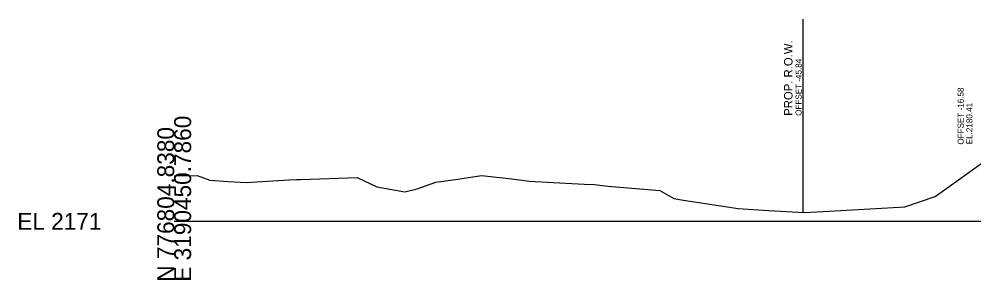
# Model space of a CAD drawing. Extents: x -26 to 303, y -25 to 5046.
# Drawn here: x -25.7 to 132.5, y 3990.3 to 4033.5 of the extents above; entities that cross this region are included whole.
import ezdxf

# ---------------------------------------------------------------- set-up
doc = ezdxf.new("R2010")
doc.units = 0
for name, color, linetype in [('DESIGN - ROW - Right-of-Way and Easement Labels', 7, 'Continuous'), ('DESIGN - ROW - Right-of-Way Linework', 7, 'Continuous'), ('DESIGN - SHEET - Light Grid', 7, 'Continuous'), ('DESIGN - TYPICAL - Slope Tie Text', 7, 'Continuous'), ('SURVEY - GROUND - Top of Ground', 7, 'Continuous')]:
    doc.layers.add(name, color=color, linetype=linetype)

msp = doc.modelspace()

# ---------------------------------------------------------------- linework, layer by layer
at = {"layer": 'DESIGN - ROW - Right-of-Way Linework'}
msp.add_line((104.16, 4001.47), (104.16, 4033.47), dxfattribs=at)
at = {"layer": 'DESIGN - SHEET - Light Grid'}
msp.add_line((0, 4000), (150, 4000), dxfattribs=at)
at = {"layer": 'SURVEY - GROUND - Top of Ground'}
msp.add_lwpolyline([(0, 4007.52), (3.82, 4007.56), (5.92, 4006.81), (8.92, 4006.59), (11.91, 4006.41), (19.01, 4006.85), (20.28, 4006.94), (20.95, 4006.95), (30.32, 4007.23), (33.55, 4005.73), (38.22, 4004.89), (40.24, 4005.39), (43.36, 4006.46), (47, 4007), (50.9, 4007.57), (55.92, 4007.05), (58.79, 4006.65), (67.91, 4006.16), (69.61, 4006.12), (71.8, 4005.84), (80.41, 4005.13), (82.78, 4003.76), (84.37, 4003.48), (93.43, 4002.15), (98.43, 4001.78), (104.33, 4001.46), (108.47, 4001.66), (121.04, 4002.41), (126.05, 4004.12), (126.45, 4004.39), (134.74, 4010.36)], dxfattribs=at)

# ---------------------------------------------------------------- texts
at = {"layer": 'DESIGN - ROW - Right-of-Way and Easement Labels'}
for s, height, p in [('PROP. R.O.W.', 1.4, (102.41, 4017.47)), ('OFFSET -45.84', 1, (103.91, 4017.47))]:
    msp.add_text(s, height=height, rotation=90, dxfattribs=at).set_placement(p)
at = {"layer": 'DESIGN - SHEET - Light Grid'}
for s, p in [('E 3190450.7860', (2.8, 3990)), ('N 776804.8380', (0, 3990))]:
    msp.add_text(s, height=2.8, rotation=90, dxfattribs=at).set_placement(p)
msp.add_text('EL 2171', height=2.8, dxfattribs=at).set_placement((-26, 3998.6))
at = {"layer": 'DESIGN - TYPICAL - Slope Tie Text'}
for s, p in [('OFFSET -16.58', (130.76, 4012.7)), ('EL.2180.41', (132.21, 4012.76))]:
    msp.add_text(s, height=1, rotation=90, dxfattribs=at).set_placement(p)

doc.saveas('drawing.dxf')
